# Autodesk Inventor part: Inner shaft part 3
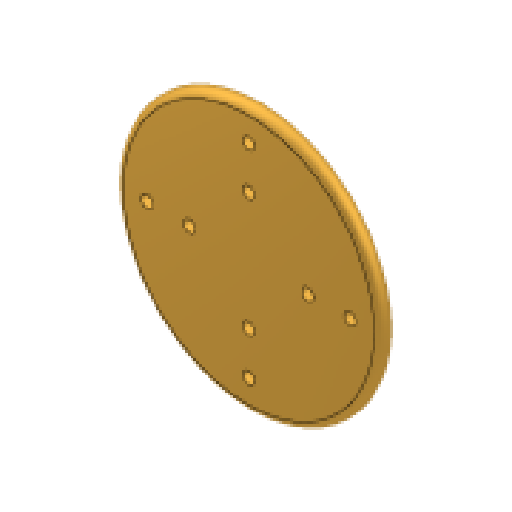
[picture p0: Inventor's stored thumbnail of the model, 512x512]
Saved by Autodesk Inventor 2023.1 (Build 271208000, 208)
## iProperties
Created: 2020-02
Part Number: Inner shaft part 3
Material: Brass, Soft Yellow
Document SubType Name: Modeling
Designer: ftrauzettel
Density: 8.47 g/cm^3
Appearance: Brass - Satin
Sending System: SolidWorks 2016
Last Author: Pam
Last Saved: 2020-02-24
Author: ftrauzettel
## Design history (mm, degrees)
feature "Tap Drill Slot for M2 Tap1"
body "Solid1"
